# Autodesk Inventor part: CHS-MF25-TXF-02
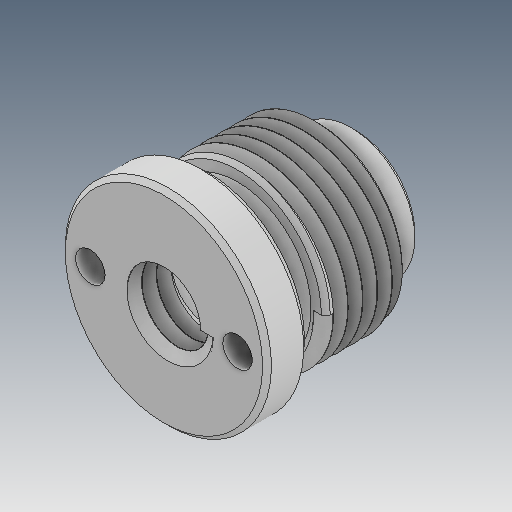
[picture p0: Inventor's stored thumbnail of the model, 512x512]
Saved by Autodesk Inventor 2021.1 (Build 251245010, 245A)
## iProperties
Created: 2019-04
Part Number: CHS-MF25-TXF-02
Material: Ogólny
Document SubType Name: Modeling
Designer: user
Density: 1 g/cm^3
Appearance: Domyślna
Author: user
Revision Number: ÈÎºÎ
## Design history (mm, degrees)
feature "ÊäÈë1"
node "Bryła1"
